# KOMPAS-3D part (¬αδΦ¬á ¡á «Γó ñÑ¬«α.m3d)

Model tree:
1. Эскиз:2
2. Операция выдавливания:2
     Расстояние 1 = 2
3. Эскиз:3
4. Вырезать элемент выдавливания:1
     Расстояние 1 = 10
5. Эскиз:4
6. Операция выдавливания:3
     Расстояние 1 = 13
7. Эскиз:5
8. Вырезать элемент выдавливания:2
     Расстояние 2 = 80; Расстояние 1 = 10
